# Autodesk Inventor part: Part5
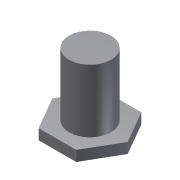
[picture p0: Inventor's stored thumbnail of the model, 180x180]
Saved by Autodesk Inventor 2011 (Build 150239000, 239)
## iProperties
Created: 2008-05
Part Number: Part5
Document SubType Name: Modeling
Designer: CADCIM
Density: 1 g/cm^3
Author: CADCIM
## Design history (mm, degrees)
sketch "Sketch1"
  geometry: C1 r 2 at (-7.12, 11.618)
  constraints: 1 centre point
  dimensions: "d2" = 4 diameter of C1
extrude "Extrusion1" new body sketch "Sketch1" distance "d0" = 6; taper "d1" = 0 deg
sketch "Sketch2"
  geometry: L1 (-3.598, 0)-(-1.799, 3.116); L2 (-1.799, 3.116)-(1.799, 3.116); L3 (1.799, 3.116)-(3.598, 0); L4 (3.598, 0)-(1.799, -3.116); L5 (1.799, -3.116)-(-1.799, -3.116); L6 (-1.799, -3.116)-(-3.598, 0); C1 r 2 at (0, 0) reference; 1 further point
  constraints: 12 end point, 1 coincident, 13 other
extrude "Extrusion2" join sketch "Sketch2" distance "d3" = 1; taper "d4" = 0 deg
body "Solid1"
